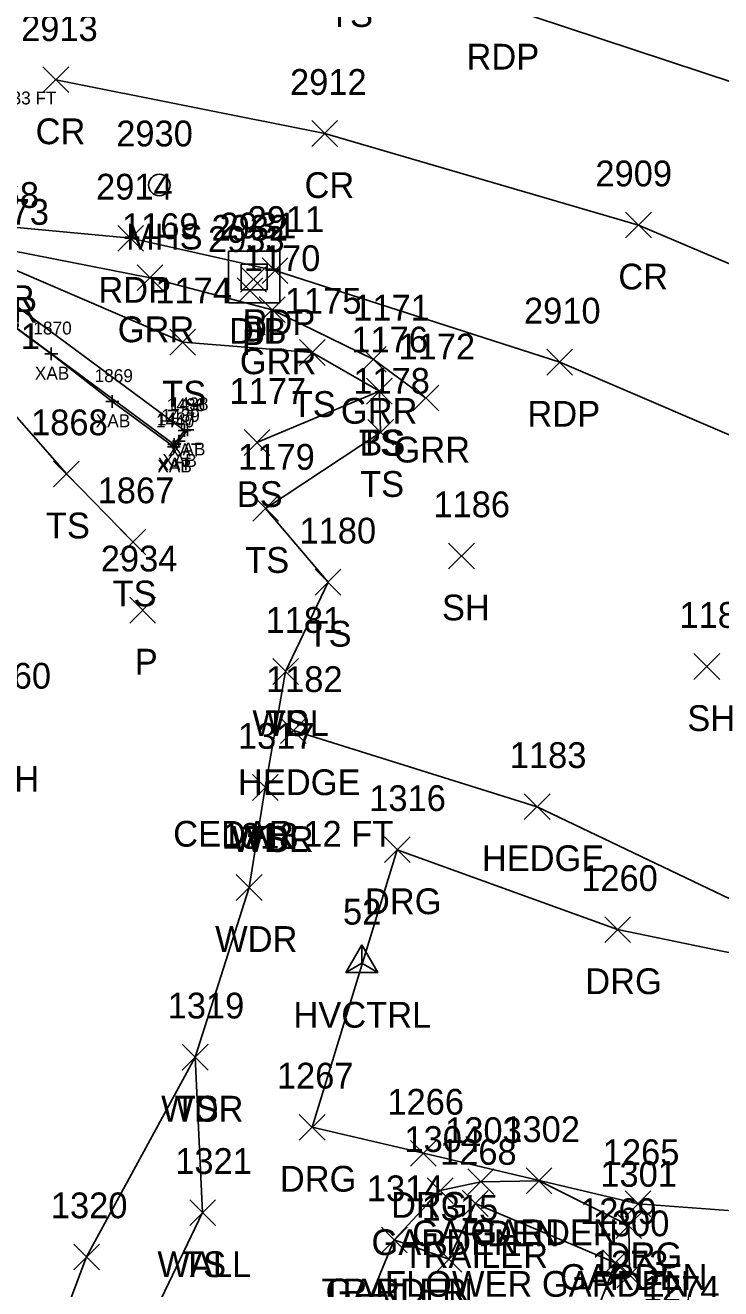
# Model space of a CAD drawing. Extents: x 1638344 to 1639591, y 610835 to 612202.
# Drawn here: x 1638740.9 to 1638794.9, y 611608.8 to 611706.8 of the extents above; entities that cross this region are included whole.
import ezdxf

# ---------------------------------------------------------------- set-up
doc = ezdxf.new("R2010")
doc.units = 0
for name, color, linetype in [('B_A', 7, 'Continuous'), ('B_C', 7, 'Continuous'), ('B_I', 7, 'Continuous'), ('B_TIC', 7, 'Continuous'), ('BSUBM', 7, 'Continuous'), ('C_A', 7, 'Continuous'), ('C_I', 7, 'Continuous'), ('CPSM', 7, 'Continuous'), ('D_A', 7, 'Continuous'), ('D_I', 7, 'Continuous'), ('D_TIC', 7, 'Continuous'), ('DS', 7, 'Continuous'), ('L_A', 7, 'Continuous'), ('L_C', 7, 'Continuous'), ('L_I', 7, 'Continuous'), ('L_TIC', 7, 'Continuous'), ('LAHR', 7, 'Continuous'), ('LAPB', 7, 'Continuous'), ('LAWA', 7, 'Continuous'), ('LBC', 7, 'Continuous'), ('LELB', 7, 'Continuous'), ('LW', 7, 'Continuous'), ('P_A', 7, 'Continuous'), ('P_I', 7, 'Continuous'), ('P_TIC', 7, 'Continuous'), ('PET', 7, 'Continuous'), ('PRC', 7, 'Continuous'), ('R_A', 7, 'Continuous'), ('R_I', 7, 'Continuous'), ('R_TIC', 7, 'Continuous'), ('RDG', 7, 'Continuous'), ('RGR', 7, 'Continuous'), ('U_A', 7, 'Continuous'), ('U_C', 7, 'Continuous'), ('U_I', 7, 'Continuous'), ('USMH', 7, 'Continuous')]:
    doc.layers.add(name, color=color, linetype=linetype)

msp = doc.modelspace()

# ---------------------------------------------------------------- linework, layer by layer
at = {"layer": 'B_TIC'}
for p, q in [((1638742.911, 611681.311), (1638742.986, 611681.311)), ((1638747.645, 611677.616), (1638747.72, 611677.616)), ((1638753.253, 611675.359), (1638753.329, 611675.359)), ((1638753.48, 611675.427), (1638753.555, 611675.427)), ((1638752.423, 611674.105), (1638752.498, 611674.105)), ((1638752.455, 611674.266), (1638752.531, 611674.266)), ((1638752.455, 611674.266), (1638752.531, 611674.266)), ((1638752.814, 611674.536), (1638752.89, 611674.536))]:
    msp.add_line(p, q, dxfattribs=at)
for points in [[(1638742.907, 611680.811), (1638742.907, 611681.811)], [(1638742.407, 611681.311), (1638743.407, 611681.311)], [(1638747.141, 611677.616), (1638748.141, 611677.616)], [(1638747.641, 611677.116), (1638747.641, 611678.116)], [(1638753.25, 611674.859), (1638753.25, 611675.859)], [(1638753.476, 611674.927), (1638753.476, 611675.927)], [(1638752.419, 611673.605), (1638752.419, 611674.605)], [(1638752.452, 611673.766), (1638752.452, 611674.766)], [(1638752.452, 611673.766), (1638752.452, 611674.766)], [(1638752.75, 611675.359), (1638753.75, 611675.359)], [(1638752.811, 611674.036), (1638752.811, 611675.036)], [(1638752.976, 611675.427), (1638753.976, 611675.427)], [(1638751.919, 611674.105), (1638752.919, 611674.105)], [(1638751.952, 611674.266), (1638752.952, 611674.266)], [(1638751.952, 611674.266), (1638752.952, 611674.266)], [(1638752.311, 611674.536), (1638753.311, 611674.536)]]:
    msp.add_lwpolyline(points, dxfattribs=at)
at = {"layer": 'BSUBM'}
for points in [[(1638753.476, 611675.427), (1638752.811, 611674.536), (1638752.419, 611674.105), (1638747.641, 611677.616), (1638742.907, 611681.311), (1638734.863, 611687.18), (1638734.867, 611689.575), (1638734.66, 611707.088), (1638734.43, 611715.026)], [(1638738.119, 611684.862), (1638734.91, 611687.242), (1638734.919, 611689.138), (1638737.018, 611688.84), (1638736.732, 611687.615), (1638738.892, 611685.964), (1638753.25, 611675.359), (1638752.452, 611674.266)], [(1638738.119, 611684.862), (1638752.452, 611674.266)]]:
    msp.add_lwpolyline(points, dxfattribs=at)
at = {"layer": 'CPSM'}
for p, q in [((1638765.763, 611633.311), (1638767.013, 611635.476)), ((1638768.263, 611633.311), (1638767.013, 611635.476)), ((1638767.014, 611634.032), (1638767.013, 611635.476)), ((1638765.763, 611633.311), (1638767.014, 611634.032)), ((1638767.014, 611634.032), (1638767.014, 611634.032)), ((1638767.014, 611634.032), (1638768.263, 611633.311)), ((1638765.763, 611633.311), (1638768.263, 611633.311))]:
    msp.add_line(p, q, dxfattribs=at)
at = {"layer": 'D_TIC'}
for points in [[(1638757.606, 611686.09), (1638759.606, 611688.09)], [(1638759.606, 611686.09), (1638757.606, 611688.09)], [(1638757.327, 611685.211), (1638759.327, 611687.211)], [(1638759.327, 611685.211), (1638757.327, 611687.211)], [(1638749.007, 611660.428), (1638751.007, 611662.428)], [(1638751.007, 611660.428), (1638749.007, 611662.428)]]:
    msp.add_lwpolyline(points, dxfattribs=at)
at = {"layer": 'DS'}
for p, q in [((1638756.657, 611689.263), (1638760.657, 611689.263)), ((1638756.657, 611685.263), (1638756.657, 611689.263)), ((1638760.657, 611689.263), (1638760.657, 611685.263)), ((1638757.657, 611686.263), (1638757.657, 611688.263)), ((1638757.657, 611688.263), (1638759.657, 611688.263)), ((1638759.657, 611688.263), (1638759.657, 611686.263)), ((1638758.662, 611687.264), (1638758.662, 611687.264)), ((1638758.662, 611687.264), (1638758.662, 611687.264)), ((1638759.657, 611686.263), (1638757.657, 611686.263)), ((1638760.657, 611685.263), (1638756.657, 611685.263))]:
    msp.add_line(p, q, dxfattribs=at)
at = {"layer": 'L_TIC'}
for points in [[(1638752.11, 611681.218), (1638754.11, 611683.218)], [(1638754.11, 611681.218), (1638752.11, 611683.218)], [(1638762.165, 611680.415), (1638764.165, 611682.415)], [(1638764.165, 611680.415), (1638762.165, 611682.415)], [(1638767.38, 611677.417), (1638769.38, 611679.417)], [(1638769.38, 611677.417), (1638767.38, 611679.417)], [(1638767.38, 611677.417), (1638769.38, 611679.417)], [(1638769.38, 611677.417), (1638767.38, 611679.417)], [(1638767.471, 611674.213), (1638769.471, 611676.213)], [(1638769.471, 611674.213), (1638767.471, 611676.213)], [(1638757.867, 611673.43), (1638759.867, 611675.43)], [(1638759.867, 611673.43), (1638757.867, 611675.43)], [(1638743.074, 611670.992), (1638745.074, 611672.992)], [(1638745.074, 611670.992), (1638743.074, 611672.992)], [(1638758.548, 611668.317), (1638760.548, 611670.317)], [(1638760.548, 611668.317), (1638758.548, 611670.317)], [(1638748.245, 611665.719), (1638750.245, 611667.719)], [(1638750.245, 611665.719), (1638748.245, 611667.719)], [(1638773.749, 611664.633), (1638775.749, 611666.633)], [(1638775.749, 611664.633), (1638773.749, 611666.633)], [(1638763.389, 611662.595), (1638765.389, 611664.595)], [(1638765.389, 611662.595), (1638763.389, 611664.595)], [(1638792.797, 611656.051), (1638794.797, 611658.051)], [(1638794.797, 611656.051), (1638792.797, 611658.051)], [(1638760.099, 611655.663), (1638762.099, 611657.663)], [(1638762.099, 611655.663), (1638760.099, 611657.663)], [(1638760.099, 611655.663), (1638762.099, 611657.663)], [(1638762.099, 611655.663), (1638760.099, 611657.663)], [(1638760.697, 611651.078), (1638762.697, 611653.078)], [(1638762.697, 611651.078), (1638760.697, 611653.078)], [(1638758.52, 611646.67), (1638760.52, 611648.67)], [(1638760.52, 611646.67), (1638758.52, 611648.67)], [(1638758.52, 611646.67), (1638760.52, 611648.67)], [(1638760.52, 611646.67), (1638758.52, 611648.67)], [(1638758.52, 611646.67), (1638760.52, 611648.67)], [(1638760.52, 611646.67), (1638758.52, 611648.67)], [(1638779.628, 611645.181), (1638781.628, 611647.181)], [(1638781.628, 611645.181), (1638779.628, 611647.181)], [(1638757.265, 611638.912), (1638759.265, 611640.912)], [(1638759.265, 611638.912), (1638757.265, 611640.912)], [(1638753.075, 611625.75), (1638755.075, 611627.75)], [(1638755.075, 611625.75), (1638753.075, 611627.75)], [(1638753.075, 611625.75), (1638755.075, 611627.75)], [(1638755.075, 611625.75), (1638753.075, 611627.75)], [(1638775.251, 611616.086), (1638777.251, 611618.086)], [(1638777.251, 611616.086), (1638775.251, 611618.086)], [(1638779.773, 611616.159), (1638781.773, 611618.159)], [(1638781.773, 611616.159), (1638779.773, 611618.159)], [(1638772.095, 611615.395), (1638774.095, 611617.395)], [(1638774.095, 611615.395), (1638772.095, 611617.395)], [(1638774.825, 611614.398), (1638776.825, 611616.398)], [(1638776.825, 611614.398), (1638774.825, 611616.398)], [(1638753.653, 611613.69), (1638755.653, 611615.69)], [(1638755.653, 611613.69), (1638753.653, 611615.69)], [(1638753.653, 611613.69), (1638755.653, 611615.69)], [(1638755.653, 611613.69), (1638753.653, 611615.69)], [(1638786.734, 611612.692), (1638788.734, 611614.692)], [(1638788.734, 611612.692), (1638786.734, 611614.692)], [(1638768.53, 611611.573), (1638770.53, 611613.573)], [(1638770.53, 611611.573), (1638768.53, 611613.573)], [(1638768.53, 611611.573), (1638770.53, 611613.573)], [(1638770.53, 611611.573), (1638768.53, 611613.573)], [(1638744.651, 611610.251), (1638746.651, 611612.251)], [(1638746.651, 611610.251), (1638744.651, 611612.251)], [(1638772.778, 611610.067), (1638774.778, 611612.067)], [(1638774.778, 611610.067), (1638772.778, 611612.067)], [(1638785.704, 611609.803), (1638787.704, 611611.803)], [(1638787.704, 611609.803), (1638785.704, 611611.803)], [(1638786.799, 611608.856), (1638788.799, 611610.856)], [(1638788.799, 611608.856), (1638786.799, 611610.856)]]:
    msp.add_lwpolyline(points, dxfattribs=at)
at = {"layer": 'LAHR'}
msp.add_lwpolyline([(1638761.697, 611652.078), (1638780.628, 611646.181), (1638799.04, 611637.379)], dxfattribs=at)
at = {"layer": 'LAPB'}
msp.add_lwpolyline([(1638787.799, 611609.856), (1638787.734, 611613.692), (1638780.773, 611617.159), (1638776.251, 611617.086), (1638773.095, 611616.395), (1638769.53, 611612.573)], dxfattribs=at)
at = {"layer": 'LAWA'}
for points in [[(1638761.099, 611656.663), (1638759.52, 611647.67)], [(1638759.52, 611647.67), (1638758.265, 611639.912), (1638754.075, 611626.75), (1638745.651, 611611.251), (1638737.088, 611588.631), (1638728.542, 611569.253)]]:
    msp.add_lwpolyline(points, dxfattribs=at)
at = {"layer": 'LBC'}
for points in [[(1638775.825, 611615.398), (1638786.704, 611610.803), (1638783.104, 611601.453), (1638779.596, 611593.171), (1638773.779, 611579.177), (1638769.563, 611568.826), (1638767.87, 611565.034), (1638762.745, 611552.727), (1638751.467, 611557.412), (1638760.979, 611580.197), (1638765.562, 611591.58), (1638767.532, 611594.992), (1638769.441, 611599.08), (1638765.068, 611601.779), (1638769.53, 611612.573), (1638773.778, 611611.067)], [(1638773.778, 611611.067), (1638775.825, 611615.398)]]:
    msp.add_lwpolyline(points, dxfattribs=at)
at = {"layer": 'LELB'}
for points in [[(1638749.245, 611666.719), (1638744.074, 611671.992), (1638738.202, 611678.674), (1638732.325, 611684.966), (1638728.186, 611690.971)], [(1638738.905, 611688.319), (1638753.11, 611682.218), (1638763.165, 611681.415), (1638768.38, 611678.417), (1638768.471, 611675.213), (1638759.548, 611669.317), (1638764.389, 611663.595), (1638761.099, 611656.663), (1638759.52, 611647.67)], [(1638768.38, 611678.417), (1638758.867, 611674.43)], [(1638754.075, 611626.75), (1638754.653, 611614.69)]]:
    msp.add_lwpolyline(points, dxfattribs=at)
at = {"layer": 'LW'}
msp.add_lwpolyline([(1638754.653, 611614.69), (1638747.952, 611600.708), (1638740.356, 611579.71), (1638735.169, 611566.763)], dxfattribs=at)
at = {"layer": 'P_TIC'}
for points in [[(1638742.255, 611701.573), (1638744.255, 611703.573)], [(1638744.255, 611701.573), (1638742.255, 611703.573)], [(1638763.131, 611697.399), (1638765.131, 611699.399)], [(1638765.131, 611697.399), (1638763.131, 611699.399)], [(1638787.494, 611690.303), (1638789.494, 611692.303)], [(1638789.494, 611690.303), (1638787.494, 611692.303)], [(1638748.075, 611689.276), (1638750.075, 611691.276)], [(1638750.075, 611689.276), (1638748.075, 611691.276)], [(1638759.269, 611686.763), (1638761.269, 611688.763)], [(1638761.269, 611686.763), (1638759.269, 611688.763)], [(1638781.382, 611679.66), (1638783.382, 611681.66)], [(1638783.382, 611679.66), (1638781.382, 611681.66)]]:
    msp.add_lwpolyline(points, dxfattribs=at)
at = {"layer": 'PET'}
msp.add_lwpolyline([(1638811.617, 611668.124), (1638782.382, 611680.66), (1638760.269, 611687.763), (1638749.075, 611690.276), (1638736.887, 611691.427), (1638737.261, 611703.383), (1638737.238, 611715.506), (1638749.613, 611712.202), (1638777.651, 611708.363), (1638798.655, 611701.427), (1638823.202, 611689.416)], dxfattribs=at)
at = {"layer": 'PRC'}
msp.add_lwpolyline([(1638816.401, 611679.453), (1638788.494, 611691.303), (1638764.131, 611698.399), (1638743.255, 611702.573)], dxfattribs=at)
at = {"layer": 'R_TIC'}
for points in [[(1638749.574, 611686.211), (1638751.574, 611688.211)], [(1638751.574, 611686.211), (1638749.574, 611688.211)], [(1638759.056, 611683.731), (1638761.056, 611685.731)], [(1638761.056, 611683.731), (1638759.056, 611685.731)], [(1638766.901, 611679.888), (1638768.901, 611681.888)], [(1638768.901, 611679.888), (1638766.901, 611681.888)], [(1638770.984, 611676.88), (1638772.984, 611678.88)], [(1638772.984, 611676.88), (1638770.984, 611678.88)], [(1638768.768, 611641.842), (1638770.768, 611643.842)], [(1638770.768, 611641.842), (1638768.768, 611643.842)], [(1638768.768, 611641.842), (1638770.768, 611643.842)], [(1638770.768, 611641.842), (1638768.768, 611643.842)], [(1638785.873, 611635.64), (1638787.873, 611637.64)], [(1638787.873, 611635.64), (1638785.873, 611637.64)], [(1638762.161, 611620.314), (1638764.161, 611622.314)], [(1638764.161, 611620.314), (1638762.161, 611622.314)], [(1638770.793, 611618.289), (1638772.793, 611620.289)], [(1638772.793, 611618.289), (1638770.793, 611620.289)], [(1638787.459, 611614.375), (1638789.459, 611616.375)], [(1638789.459, 611614.375), (1638787.459, 611616.375)]]:
    msp.add_lwpolyline(points, dxfattribs=at)
at = {"layer": 'RDG'}
for points in [[(1638804.754, 611656.589), (1638801.474, 611638.763), (1638799.009, 611634.152), (1638786.873, 611636.64), (1638769.768, 611642.842)], [(1638822.207, 611647.398), (1638818.203, 611638.318), (1638813.404, 611624.175), (1638806.87, 611615.608), (1638797.555, 611614.687), (1638788.459, 611615.375), (1638771.793, 611619.289), (1638763.161, 611621.314), (1638769.768, 611642.842)]]:
    msp.add_lwpolyline(points, dxfattribs=at)
at = {"layer": 'RGR'}
msp.add_lwpolyline([(1638738.175, 611689.63), (1638750.574, 611687.211), (1638760.056, 611684.731), (1638767.901, 611680.888), (1638771.984, 611677.88)], dxfattribs=at)
at = {"layer": 'USMH'}
for p, q in [((1638751.293, 611694.403), (1638751.293, 611694.403)), ((1638752.126, 611694.403), (1638752.126, 611694.403))]:
    msp.add_line(p, q, dxfattribs=at)
msp.add_circle((1638751.293, 611694.403), 0.833, dxfattribs=at)

# ---------------------------------------------------------------- texts
at = {"layer": 'B_A'}
for s, p in [('XAB', (1638741.628, 611679.311)), ('XAB', (1638746.362, 611675.616)), ('XAT', (1638751.955, 611673.359)), ('XAB', (1638752.197, 611673.427)), ('XAB', (1638751.14, 611672.105)), ('XAT', (1638751.157, 611672.266)), ('XAT', (1638751.157, 611672.266)), ('XAB', (1638751.531, 611672.536))]:
    msp.add_text(s, height=1, dxfattribs=at).set_placement(p)
at = {"layer": 'B_C'}
msp.add_text('BRIDGE SEAT DEPTH 1.33 FT', height=1, dxfattribs=at).set_placement((1638724.439, 611700.66))
at = {"layer": 'B_I'}
for s, p in [('1870', (1638741.518, 611682.811)), ('1869', (1638746.267, 611679.116)), ('1436', (1638751.876, 611676.859)), ('1438', (1638752.13, 611676.927)), ('1440', (1638751.029, 611675.605)), ('1437', (1638751.105, 611675.766)), ('1437', (1638751.105, 611675.766)), ('1439', (1638751.461, 611676.036))]:
    msp.add_text(s, height=1, dxfattribs=at).set_placement(p)
at = {"layer": 'C_A'}
msp.add_text('HVCTRL', height=2, dxfattribs=at).set_placement((1638761.706, 611629.032))
at = {"layer": 'C_I'}
msp.add_text('52', height=2, dxfattribs=at).set_placement((1638765.549, 611637.032))
at = {"layer": 'D_A'}
for s, p in [('DIB', (1638756.708, 611682.09)), ('DI', (1638757.717, 611682.264)), ('P', (1638757.705, 611681.211)), ('P', (1638749.385, 611656.428))]:
    msp.add_text(s, height=2, dxfattribs=at).set_placement(p)
at = {"layer": 'D_I'}
for s, p in [('2931', (1638755.969, 611690.264)), ('2932', (1638755.346, 611690.09)), ('2933', (1638755.067, 611689.211)), ('2934', (1638746.747, 611664.428))]:
    msp.add_text(s, height=2, dxfattribs=at).set_placement(p)
at = {"layer": 'L_A'}
for s, p in [('TS', (1638764.46, 611706.672)), ('TS', (1638751.519, 611677.218)), ('TS', (1638761.574, 611676.415)), ('TS', (1638766.789, 611673.417)), ('BS', (1638766.821, 611673.417)), ('TS', (1638766.881, 611670.213)), ('BS', (1638757.307, 611669.43)), ('TS', (1638742.484, 611666.992)), ('TS', (1638757.957, 611664.317)), ('TS', (1638747.655, 611661.719)), ('SH', (1638773.237, 611660.633)), ('TS', (1638762.798, 611658.595)), ('SH', (1638792.285, 611652.051)), ('WDL', (1638758.516, 611651.663)), ('TS', (1638759.508, 611651.663)), ('SH', (1638738.251, 611647.336)), ('HEDGE', (1638757.398, 611647.078)), ('WDR', (1638756.882, 611642.67)), ('WDL', (1638756.937, 611642.67)), ('TS', (1638757.929, 611642.67)), ('HEDGE', (1638776.329, 611641.181)), ('WDR', (1638755.627, 611634.912)), ('WDR', (1638751.437, 611621.75)), ('TS', (1638752.485, 611621.75)), ('GARDEN', (1638770.92, 611612.086)), ('GARDEN', (1638775.442, 611612.159)), ('GARDEN', (1638767.764, 611611.395)), ('TRAILER', (1638770.179, 611610.398)), ('WALL', (1638751.141, 611609.69)), ('TS', (1638753.062, 611609.69)), ('GARDEN', (1638782.404, 611608.692)), ('TRAILER', (1638763.884, 611607.573)), ('GARDEN', (1638764.199, 611607.573))]:
    msp.add_text(s, height=2, dxfattribs=at).set_placement(p)
at = {"layer": 'L_C'}
for s, p in [('CEDAR 12 FT', (1638752.367, 611643.078)), ('FLOWER GARDEN', (1638768.812, 611608.159))]:
    msp.add_text(s, height=2, dxfattribs=at).set_placement(p)
at = {"layer": 'L_I'}
for s, p in [('1173', (1638736.779, 611691.319)), ('1174', (1638750.984, 611685.218)), ('1175', (1638761.039, 611684.415)), ('1871', (1638736.076, 611681.674)), ('1176', (1638766.199, 611681.417)), ('1176', (1638766.199, 611681.417)), ('1178', (1638766.345, 611678.213)), ('1177', (1638756.741, 611677.43)), ('1868', (1638741.334, 611674.992)), ('1179', (1638757.414, 611672.317)), ('1867', (1638746.505, 611669.719)), ('1186', (1638772.568, 611668.633)), ('1180', (1638762.176, 611666.595)), ('1185', (1638791.671, 611660.051)), ('1181', (1638759.54, 611659.663)), ('1181', (1638759.54, 611659.663)), ('1860', (1638736.936, 611655.336)), ('1182', (1638759.571, 611655.078)), ('1317', (1638757.394, 611650.67)), ('1317', (1638757.394, 611650.67)), ('1317', (1638757.394, 611650.67)), ('1183', (1638778.502, 611649.181)), ('1318', (1638756.139, 611642.912)), ('1319', (1638751.941, 611629.75)), ('1319', (1638751.941, 611629.75)), ('1303', (1638773.48, 611620.086)), ('1302', (1638778.001, 611620.159)), ('1304', (1638770.323, 611619.395)), ('1321', (1638752.527, 611617.69)), ('1321', (1638752.527, 611617.69)), ('1268', (1638773.084, 611618.398)), ('1301', (1638785.53, 611616.692)), ('1314', (1638767.404, 611615.573)), ('1314', (1638767.404, 611615.573)), ('1320', (1638742.871, 611614.251)), ('1315', (1638771.652, 611614.067)), ('1269', (1638783.956, 611613.803)), ('1300', (1638784.941, 611612.856))]:
    msp.add_text(s, height=2, dxfattribs=at).set_placement(p)
at = {"layer": 'P_A'}
for s, p in [('RDP', (1638775.139, 611703.363)), ('RDP', (1638775.139, 611703.363)), ('CR', (1638741.688, 611697.573)), ('CR', (1638762.564, 611693.399)), ('CR', (1638786.927, 611686.303)), ('RDP', (1638746.563, 611685.276)), ('RDP', (1638757.757, 611682.763)), ('RDP', (1638779.87, 611675.66))]:
    msp.add_text(s, height=2, dxfattribs=at).set_placement(p)
at = {"layer": 'P_I'}
for s, p in [('2913', (1638740.562, 611705.573)), ('2912', (1638761.438, 611701.399)), ('2909', (1638785.148, 611694.303)), ('2914', (1638746.382, 611693.276)), ('2911', (1638758.143, 611690.763)), ('2910', (1638779.602, 611683.66))]:
    msp.add_text(s, height=2, dxfattribs=at).set_placement(p)
at = {"layer": 'R_A'}
for s, p in [('GRR', (1638735.663, 611684.63)), ('GRR', (1638748.062, 611682.211)), ('GRR', (1638757.544, 611679.731)), ('GRR', (1638765.389, 611675.888)), ('GRR', (1638769.472, 611672.88)), ('DRG', (1638767.256, 611637.842)), ('DRG', (1638767.256, 611637.842)), ('DRG', (1638784.361, 611631.64)), ('DRG', (1638760.649, 611616.314)), ('DRG', (1638769.281, 611614.289)), ('DRG', (1638785.948, 611610.375))]:
    msp.add_text(s, height=2, dxfattribs=at).set_placement(p)
at = {"layer": 'R_I'}
for s, p in [('1168', (1638736.002, 611692.63)), ('1169', (1638748.393, 611690.211)), ('1170', (1638757.843, 611687.731)), ('1171', (1638766.341, 611683.888)), ('1172', (1638769.858, 611680.88)), ('1316', (1638767.587, 611645.842)), ('1316', (1638767.587, 611645.842)), ('1260', (1638784.046, 611639.64)), ('1267', (1638760.421, 611624.314)), ('1266', (1638768.997, 611622.289)), ('1265', (1638785.719, 611618.375)), ('1273', (1638784.864, 611609.728)), ('1274', (1638788.834, 611607.782))]:
    msp.add_text(s, height=2, dxfattribs=at).set_placement(p)
at = {"layer": 'U_A'}
msp.add_text('MHS', height=2, dxfattribs=at).set_placement((1638748.71, 611689.403))
at = {"layer": 'U_C'}
msp.add_text('8 IN SEWER', height=2, dxfattribs=at).set_placement((1638726.403, 611683.726))
at = {"layer": 'U_I'}
msp.add_text('2930', height=2, dxfattribs=at).set_placement((1638747.947, 611697.403))

doc.saveas('drawing.dxf')
